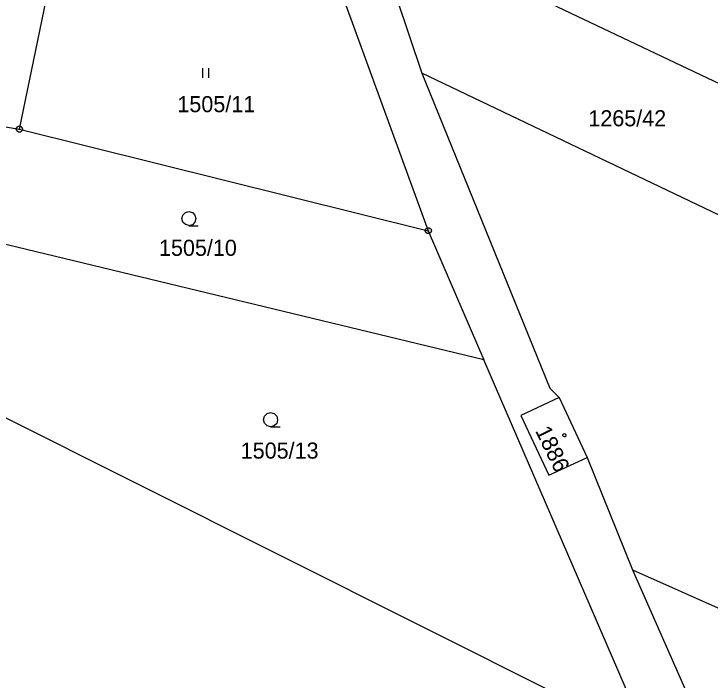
# Model space of a CAD drawing. Extents: x -779618 to -776429, y -1144546 to -1143350.
# Drawn here: x -777296 to -777222.5, y -1144048.7 to -1143978.4 of the extents above; entities that cross this region are included whole.
import ezdxf

# ---------------------------------------------------------------- set-up
doc = ezdxf.new("R2010")
doc.units = 0
for name, color, linetype in [('1', 7, 'Continuous'), ('12', 7, 'Continuous'), ('2', 7, 'Continuous'), ('3', 7, 'Continuous'), ('5', 7, 'Continuous'), ('8', 7, 'Continuous')]:
    doc.layers.add(name, color=color, linetype=linetype)

msp = doc.modelspace()

# ---------------------------------------------------------------- linework, layer by layer
at = {"layer": '1'}
for p, q in [((-777258.48, -1143968.19), (-777252.93, -1143984.66)), ((-777258.48, -1143968.19), (-777214.18, -1143989.29)), ((-777295.44, -1143990.58), (-777292.6, -1143976.92)), ((-777261.12, -1143977.11), (-777252.26, -1144001.3)), ((-777176.95, -1144020.96), (-777252.93, -1143984.66)), ((-777252.93, -1143984.66), (-777239.41, -1144017.93)), ((-777299.22, -1143989.94), (-777295.44, -1143990.58)), ((-777295.44, -1143990.58), (-777252.26, -1144001.3)), ((-777246.41, -1144014.94), (-777301.08, -1144001.76)), ((-777252.26, -1144001.3), (-777246.41, -1144014.94)), ((-777229.85, -1144053.13), (-777246.41, -1144014.94)), ((-777230.01, -1144054.53), (-777303.88, -1144017.57)), ((-777239.41, -1144017.93), (-777238.44, -1144018.91)), ((-777238.44, -1144018.91), (-777242.48, -1144020.79)), ((-777238.44, -1144018.91), (-777235.49, -1144025.23)), ((-777242.48, -1144020.79), (-777239.52, -1144027.11)), ((-777239.52, -1144027.11), (-777235.49, -1144025.23)), ((-777235.49, -1144025.23), (-777230.69, -1144037.07)), ((-777230.69, -1144037.07), (-777205.57, -1144048.32)), ((-777230.69, -1144037.07), (-777221.2, -1144058.56))]:
    msp.add_line(p, q, dxfattribs=at)
at = {"layer": '12'}
for p, q in [((-777238.44, -1144018.91), (-777242.48, -1144020.79)), ((-777238.44, -1144018.91), (-777235.49, -1144025.23)), ((-777242.48, -1144020.79), (-777239.52, -1144027.11)), ((-777239.52, -1144027.11), (-777235.49, -1144025.23))]:
    msp.add_line(p, q, dxfattribs=at)
at = {"layer": '3'}
for p, q in [((-777276.095, -1143984.155), (-777276.095, -1143985.16)), ((-777275.425, -1143985.16), (-777275.425, -1143984.155))]:
    msp.add_line(p, q, dxfattribs=at)
for points in [[(-777277.53, -1144000.75), (-777277.91, -1144000.65), (-777278.18, -1144000.38), (-777278.28, -1144000.01), (-777278.18, -1143999.64), (-777277.91, -1143999.37), (-777277.54, -1143999.27), (-777277.17, -1143999.37), (-777276.9, -1143999.64), (-777276.8, -1144000.02), (-777276.9, -1144000.4), (-777277.17, -1144000.67), (-777277.55, -1144000.77), (-777276.55, -1144000.77)], [(-777268.9, -1144021.98), (-777269.28, -1144021.88), (-777269.55, -1144021.61), (-777269.65, -1144021.24), (-777269.55, -1144020.87), (-777269.28, -1144020.6), (-777268.91, -1144020.5), (-777268.54, -1144020.6), (-777268.27, -1144020.87), (-777268.17, -1144021.25), (-777268.27, -1144021.63), (-777268.54, -1144021.9), (-777268.92, -1144022), (-777267.92, -1144022)]]:
    msp.add_lwpolyline(points, dxfattribs=at)
at = {"layer": '5'}
msp.add_lwpolyline([(-777237.89, -1144022.71), (-777237.79, -1144022.73), (-777237.74, -1144022.82), (-777237.72, -1144022.88), (-777237.74, -1144022.97), (-777237.82, -1144023.04), (-777237.89, -1144023.05), (-777237.98, -1144023.02), (-777238.04, -1144022.96), (-777238.06, -1144022.88), (-777238.04, -1144022.79), (-777237.96, -1144022.72)], close=True, dxfattribs=at)
at = {"layer": '8'}
for p, q in [((-777295.52, -1143990.58), (-777295.36, -1143990.58)), ((-777252.34, -1144001.3), (-777252.18, -1144001.3))]:
    msp.add_line(p, q, dxfattribs=at)
for points in [[(-777295.34, -1143990.258), (-777295.172, -1143990.379), (-777295.105, -1143990.573), (-777295.172, -1143990.768), (-777295.34, -1143990.888), (-777295.547, -1143990.888), (-777295.715, -1143990.768), (-777295.782, -1143990.573), (-777295.715, -1143990.379), (-777295.547, -1143990.258)], [(-777252.16, -1144000.978), (-777251.992, -1144001.099), (-777251.925, -1144001.293), (-777251.992, -1144001.488), (-777252.16, -1144001.608), (-777252.367, -1144001.608), (-777252.535, -1144001.488), (-777252.602, -1144001.293), (-777252.535, -1144001.099), (-777252.367, -1144000.978)]]:
    msp.add_lwpolyline(points, close=True, dxfattribs=at)

# ---------------------------------------------------------------- texts
at = {"layer": '2'}
for s, p in [('1505/11', (-777278.757, -1143988.79)), ('1265/42', (-777235.357, -1143990.28)), ('1505/10', (-777280.697, -1144003.95)), ('1505/13', (-777272.067, -1144025.35))]:
    msp.add_text(s, height=1.7, dxfattribs=at).set_placement(p)
msp.add_text('1886', height=1.7, rotation=295.81811, dxfattribs=at).set_placement((-777240.999, -1144022.404))

doc.saveas('drawing.dxf')
